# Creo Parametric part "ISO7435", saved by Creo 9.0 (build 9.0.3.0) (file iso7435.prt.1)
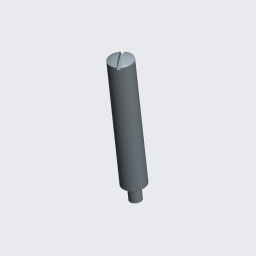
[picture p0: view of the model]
Units: Custom; MM, POUND, SECS

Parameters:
  BASIC_DIA = "0"
  PLACEMENT = "A"

Other parameters: D5, D0, D2, D19, D18, D17, THREADS_PER_INCH

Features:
  1. datum plane "DTM1"
  2. datum plane "DTM2"
  3. cut
  4. datum plane "DTM3"

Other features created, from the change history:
  component interface "Komponentenschnittstelle ID 232"

Other named items: THRU

Layers: 32, EBENEN, FLAECHEN, FLAECHENVERBUND, GEOM.ELEMENT, KONSTR.ELEMENT, NICHT.GEOM_ELEM

Family table entries: ISO7435_M1_6, ISO7435, value(s_val), 1_6, value(d_val), value(i_val), ISO7435_M2, ISO7435, 2/ , &_ISO7435_M2, &PRO_MP_CSYS, data(checksum_info), ISO7435_M2_5, ISO7435, &2.5, ISO7435_M3, ISO7435, 2/ , &_ISO7435_M3, &PRO_MP_CSYS, ISO7435_M3X6, ISO7435, &_ISO7435_M3X6, &PRO_MP_CSYS, ISO7435_M3X10, ISO7435, 2/$, ISO7435_M3_5, ISO7435, &3.5, ISO7435_M4, ISO7435, ISO7435_M5, ISO7435, ISO7435_M6, ISO7435, ISO7435_M8, ISO7435, )/ , ISO7435_M10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

Surfaces: 6 cylinder, 4 plane, 2 cone, 1 torus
